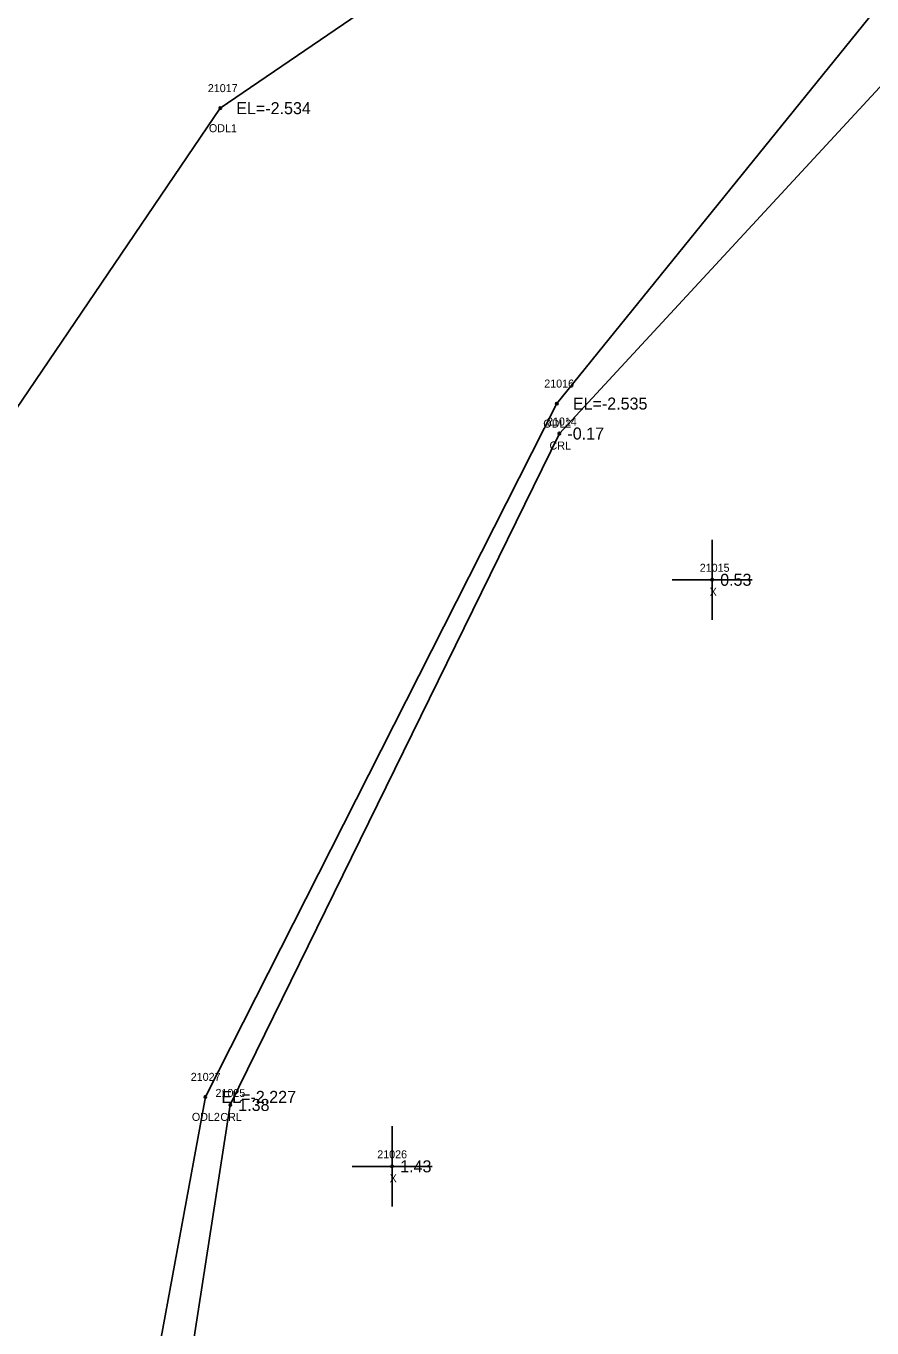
# Model space of a CAD drawing. Extents: x 2608745 to 2610333, y 641917 to 643463.
# Drawn here: x 2609261.4 to 2609367, y 642340.3 to 642503 of the extents above; entities that cross this region are included whole.
import ezdxf

# ---------------------------------------------------------------- set-up
doc = ezdxf.new("R2010")
doc.units = 0
for name, color, linetype in [('RD_EX_H2O', 7, 'Continuous'), ('RD_EX_H2O_txCode', 7, 'Continuous'), ('RD_EX_Misc', 7, 'Continuous'), ('RD_EX_Misc_txCode', 7, 'Continuous'), ('RD_EX_TX_H2O_ELEV', 7, 'Continuous'), ('RD_EX_TX_Misc_ELEV', 7, 'Continuous'), ('RD_SMD_Locator', 7, 'Continuous')]:
    doc.layers.add(name, color=color, linetype=linetype)

msp = doc.modelspace()

# ---------------------------------------------------------------- linework, layer by layer
at = {"layer": 'RD_EX_H2O'}
for points in [[(2609920.46, 642991.11), (2609852.12, 642929.11), (2609767.83, 642874.99), (2609693.3, 642807.6), (2609634.08, 642753.09), (2609556.79, 642686.91), (2609524.97, 642657.54), (2609444.81, 642602.16), (2609373.09, 642552.33), (2609285.68, 642492.71), (2609230.49, 642411.33), (2609205.38, 642280.88)], [(2609940.72, 642981.52), (2609865.8, 642912.86), (2609792.29, 642852.87), (2609723.77, 642786.36), (2609663.25, 642717.18), (2609610.37, 642689.46), (2609581.45, 642670.47), (2609545.26, 642637.18), (2609509.19, 642582.86), (2609482.73, 642569.2), (2609408.72, 642506.3), (2609370.25, 642508.5), (2609327.7, 642455.81), (2609283.83, 642369.21), (2609262.12, 642251.22)], [(2609406.01, 642432.38), (2609381.6, 642452.33), (2609371.05, 642498.63), (2609328.02, 642452.07), (2609286.93, 642368.2), (2609268.07, 642246.5)]]:
    msp.add_lwpolyline(points, dxfattribs=at)
at = {"layer": 'RD_EX_Misc'}
for p, q in [((2609347.09, 642428.8), (2609347.09, 642438.8)), ((2609342.09, 642433.8), (2609352.09, 642433.8)), ((2609307.14, 642355.53), (2609307.14, 642365.53)), ((2609302.14, 642360.53), (2609312.14, 642360.53))]:
    msp.add_line(p, q, dxfattribs=at)
at = {"layer": 'RD_SMD_Locator'}
for centre in [(2609285.68, 642492.71), (2609327.7, 642455.81), (2609328.02, 642452.07), (2609347.09, 642433.8), (2609283.83, 642369.21), (2609286.93, 642368.2), (2609307.14, 642360.53)]:
    msp.add_circle(centre, 0.15, dxfattribs=at)

# ---------------------------------------------------------------- texts
at = {"layer": 'RD_EX_H2O_txCode'}
for s, p in [('21017', (2609284.13, 642494.71)), ('ODL1', (2609284.27, 642489.71)), ('21016', (2609326.13, 642457.81)), ('ODL2', (2609326.01, 642452.81)), ('21014', (2609326.47, 642453.07)), ('CRL', (2609326.79, 642450.07)), ('21027', (2609282, 642371.21)), ('21025', (2609285.09, 642369.2)), ('ODL2', (2609282.14, 642366.21)), ('CRL', (2609285.7, 642366.2))]:
    msp.add_text(s, height=1, dxfattribs=at).set_placement(p)
at = {"layer": 'RD_EX_Misc_txCode'}
for s, p in [('21015', (2609345.54, 642434.8)), ('X', (2609346.78, 642431.8)), ('21026', (2609305.28, 642361.53)), ('X', (2609306.83, 642358.53))]:
    msp.add_text(s, height=1, dxfattribs=at).set_placement(p)
at = {"layer": 'RD_EX_TX_H2O_ELEV'}
for s, p in [('EL=-2.534', (2609287.68, 642491.96)), ('EL=-2.535', (2609329.7, 642455.06)), ('-0.17', (2609329.02, 642451.32)), ('EL=-2.227', (2609285.83, 642368.46)), ('1.38', (2609287.93, 642367.45))]:
    msp.add_text(s, height=1.5, dxfattribs=at).set_placement(p)
at = {"layer": 'RD_EX_TX_Misc_ELEV'}
for s, p in [('0.53', (2609348.09, 642433.05)), ('1.43', (2609308.14, 642359.78))]:
    msp.add_text(s, height=1.5, dxfattribs=at).set_placement(p)

doc.saveas('drawing.dxf')
